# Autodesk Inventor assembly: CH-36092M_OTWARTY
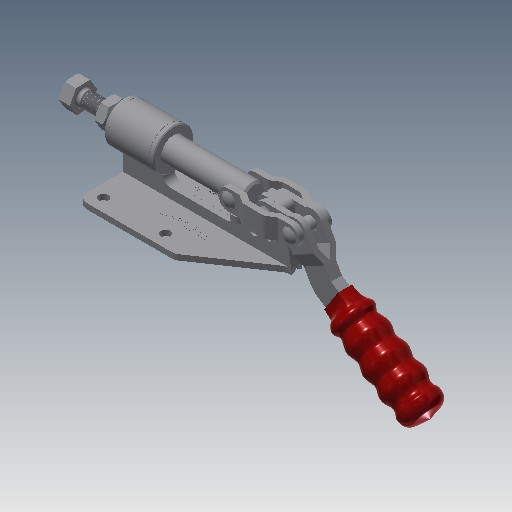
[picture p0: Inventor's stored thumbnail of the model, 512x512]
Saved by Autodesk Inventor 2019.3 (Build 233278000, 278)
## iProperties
Company: Î¢ÈíÖÐ¹ú
Created: 2012-09
Part Number: CH-36092M_OTWARTY
Material: Ogólny
Description: STEP AP203
Document SubType Name: Assembly
Designer: CADENGINEERING4
Sending System: SolidWorks 2010
Preprocessor: SwSTEP 2.0
Title: CH-36092M.STEP
Author: Î¢ÈíÓÃ»§
Revision Number: ÈÎºÎ
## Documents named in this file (14)
- D:\Vault_2016\Projekty\STRONA\Push-pull clamp\CH-36092M\CH-36092M_OTWARTY.iam
- D:\Vault_2016\Projekty\STRONA\Push-pull clamp\CH-36092M\CH-36092-11.ipt
- D:\Vault_2016\Projekty\STRONA\Push-pull clamp\CH-36092M\CH-36092-09.ipt
- D:\Vault_2016\Projekty\STRONA\Push-pull clamp\CH-36092M\CH-SA-085012 SPINDLE SUPPLIED.ipt
- D:\Vault_2016\Projekty\STRONA\Push-pull clamp\CH-36092M\CH-36092-05 LEAD SET.ipt
- D:\Vault_2016\Projekty\STRONA\Push-pull clamp\CH-36092M\CH-36092-01 BASE.ipt
- D:\Vault_2016\Projekty\STRONA\Push-pull clamp\CH-36092M\CH-302-FM-09.ipt
- D:\Vault_2016\Projekty\STRONA\Push-pull clamp\CH-36092M\CH-36092-04 CONNECTING-PLATE.ipt
- D:\Vault_2016\Projekty\STRONA\Push-pull clamp\CH-36092M\CH-36092-07.ipt
- D:\Vault_2016\Projekty\STRONA\Push-pull clamp\CH-36092M\M8 Nut.ipt
- D:\Vault_2016\Projekty\STRONA\Push-pull clamp\CH-36092M\CH-36092-03 HANDLE.ipt
- D:\Vault_2016\Projekty\STRONA\Push-pull clamp\CH-36092M\CH-36092-10.ipt
- D:\Vault_2016\Projekty\STRONA\Push-pull clamp\CH-36092M\CH-36092-02 CREST STALK .ipt
- D:\Vault_2016\Projekty\STRONA\Push-pull clamp\CH-36092M\CH-36092-06.ipt
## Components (15 placed, 15 different names)
1. CH-36092-11_1 — Równoległe:1, Zestawiające:1, Przejściowe:1
2. CH-36092-09_2 — Zestawiające:22, Zestawiające:27
3. CH-SA-085012 SPINDLE SUPPLIED_3 — Zestawiające:2, Zestawiające:3, Zestawiające:5
4. CH-36092-05 LEAD SET_4 — Zestawiające:19, Zestawiające:20, Zestawiające:21
5. CH-36092-01 BASE_5 — Równoległe:1, Zestawiające:1, Zestawiające:9, Równoległe:2, Zestawiające:12, Zestawiające:19, Zestawiające:20
6. CH-302-FM-09_6 — Zestawiające:6, Zestawiające:7, Zestawiające:8
7. CH-36092-04 CONNECTING-PLATE_7 — Zestawiające:13, Zestawiające:15, Zestawiające:16
8. CH-36092-07_8 — Zestawiające:23, Zestawiające:26
9. M8 Nut_9 — Zestawiające:2, Zestawiające:3, Zestawiające:4
10. CH-36092-07_10 — Zestawiające:24, Zestawiające:25
11. CH-36092-03 HANDLE_11 — Zestawiające:6, Zestawiające:7, Zestawiające:8, Zestawiające:10, Równoległe:3, Zestawiające:11, Zestawiające:12, Zestawiające:13, Zestawiające:14, Zestawiające:27, Przejściowe:1
12. CH-36092-10_12 — Zestawiające:10, Równoległe:3, Zestawiające:17, Zestawiające:23
13. CH-36092-02 CREST STALK _13 — Zestawiające:4, Zestawiające:5, Zestawiające:18, Zestawiające:21, Zestawiające:24
14. CH-36092-04 CONNECTING-PLATE_14 — Zestawiające:14, Zestawiające:15, Zestawiające:16, Zestawiające:17, Zestawiające:18, Zestawiające:25, Zestawiające:26
15. CH-36092-06_15 — Zestawiające:9, Równoległe:2, Zestawiające:11, Zestawiające:22
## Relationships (31: Mate 27, Flush 3, Transitional 1)
- Równoległe:1 [Flush]: CH-36092-11_1 ↔ CH-36092-01 BASE_5
- Zestawiające:1 [Mate]: CH-36092-11_1 ↔ CH-36092-01 BASE_5
- Zestawiające:2 [Mate]: CH-SA-085012 SPINDLE SUPPLIED_3 ↔ M8 Nut_9
- Zestawiające:3 [Mate]: CH-SA-085012 SPINDLE SUPPLIED_3 ↔ M8 Nut_9
- Zestawiające:4 [Mate]: M8 Nut_9 ↔ CH-36092-02 CREST STALK _13
- Zestawiające:5 [Mate]: CH-SA-085012 SPINDLE SUPPLIED_3 ↔ CH-36092-02 CREST STALK _13
- Zestawiające:6 [Mate]: CH-302-FM-09_6 ↔ CH-36092-03 HANDLE_11
- Zestawiające:7 [Mate]: CH-302-FM-09_6 ↔ CH-36092-03 HANDLE_11
- Zestawiające:8 [Mate]: CH-302-FM-09_6 ↔ CH-36092-03 HANDLE_11
- Zestawiające:9 [Mate]: CH-36092-01 BASE_5 ↔ CH-36092-06_15
- Równoległe:2 [Flush]: CH-36092-01 BASE_5 ↔ CH-36092-06_15
- Zestawiające:10 [Mate]: CH-36092-03 HANDLE_11 ↔ CH-36092-10_12
- Równoległe:3 [Flush]: CH-36092-03 HANDLE_11 ↔ CH-36092-10_12
- Zestawiające:11 [Mate]: CH-36092-03 HANDLE_11 ↔ CH-36092-06_15
- Zestawiające:12 [Mate]: CH-36092-01 BASE_5 ↔ CH-36092-03 HANDLE_11
- Zestawiające:13 [Mate]: CH-36092-04 CONNECTING-PLATE_7 ↔ CH-36092-03 HANDLE_11
- Zestawiające:14 [Mate]: CH-36092-03 HANDLE_11 ↔ CH-36092-04 CONNECTING-PLATE_14
- Zestawiające:15 [Mate]: CH-36092-04 CONNECTING-PLATE_7 ↔ CH-36092-04 CONNECTING-PLATE_14
- Zestawiające:16 [Mate]: CH-36092-04 CONNECTING-PLATE_7 ↔ CH-36092-04 CONNECTING-PLATE_14
- Zestawiające:17 [Mate]: CH-36092-10_12 ↔ CH-36092-04 CONNECTING-PLATE_14
- Zestawiające:18 [Mate]: CH-36092-02 CREST STALK _13 ↔ CH-36092-04 CONNECTING-PLATE_14
- Zestawiające:19 [Mate]: CH-36092-05 LEAD SET_4 ↔ CH-36092-01 BASE_5
- Zestawiające:20 [Mate]: CH-36092-05 LEAD SET_4 ↔ CH-36092-01 BASE_5
- Zestawiające:21 [Mate]: CH-36092-05 LEAD SET_4 ↔ CH-36092-02 CREST STALK _13
- Zestawiające:22 [Mate]: CH-36092-09_2 ↔ CH-36092-06_15
- Zestawiające:23 [Mate]: CH-36092-07_8 ↔ CH-36092-10_12
- Zestawiające:24 [Mate]: CH-36092-07_10 ↔ CH-36092-02 CREST STALK _13
- Zestawiające:25 [Mate]: CH-36092-07_10 ↔ CH-36092-04 CONNECTING-PLATE_14
- Zestawiające:26 [Mate]: CH-36092-07_8 ↔ CH-36092-04 CONNECTING-PLATE_14
- Zestawiające:27 [Mate]: CH-36092-09_2 ↔ CH-36092-03 HANDLE_11
- Przejściowe:1 [Transitional]: CH-36092-11_1 ↔ CH-36092-03 HANDLE_11
